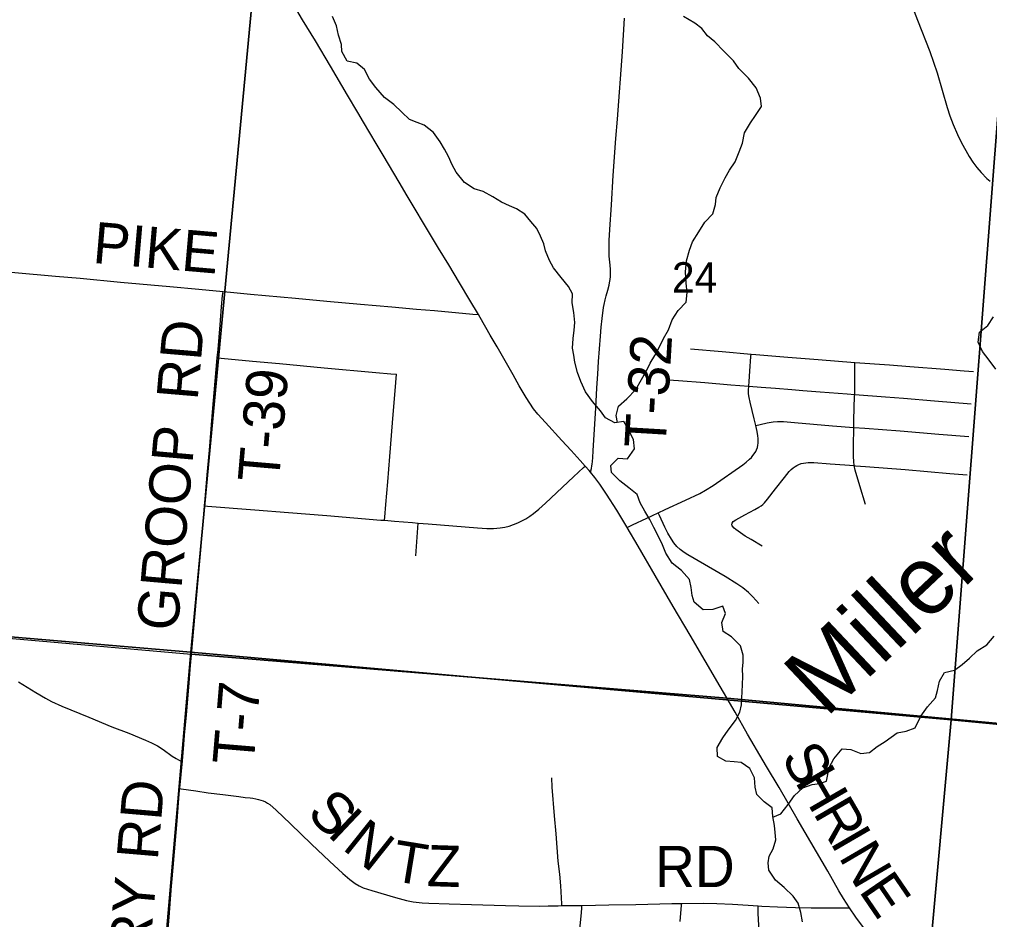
# Model space of a CAD drawing. Extents: x 0 to 1134, y 0 to 440.
# Drawn here: x 427.82 to 467.94, y 264.26 to 301.49 of the extents above; entities that cross this region are included whole.
import ezdxf

# ---------------------------------------------------------------- set-up
doc = ezdxf.new("R2010")
doc.units = 0
for name, color, linetype in [('GM_X_County_Road', 7, 'Continuous'), ('GM_X_County_Road_Text', 7, 'Continuous'), ('GM_X_Minor_River', 7, 'Continuous'), ('GM_X_Minor_River_Text', 7, 'Continuous'), ('GM_X_Section', 7, 'Continuous'), ('GM_X_Section_Text', 7, 'Continuous'), ('GM_X_Township', 7, 'Continuous'), ('GM_X_Township_Road', 7, 'Continuous'), ('GM_X_Township_Road_Text', 7, 'Continuous'), ('GM_X_Unincorporated', 7, 'Continuous')]:
    doc.layers.add(name, color=color, linetype=linetype)

msp = doc.modelspace()

# ---------------------------------------------------------------- linework, layer by layer
at = {"layer": 'GM_X_County_Road'}
for points in [[(446.801, 289.285), (446.446, 289.881), (446.016, 290.601), (445.575, 291.337), (445.153, 292.037), (444.864, 292.516), (443.858, 294.194), (443.525, 294.755), (442.86, 295.876), (442.574, 296.356), (442.054, 297.238), (441.818, 297.64), (441.388, 298.36), (440.68, 299.564), (440.063, 300.607), (439.53, 301.482), (439.195, 302.041), (438.86, 302.601), (438.148, 303.803), (437.714, 304.521), (437.366, 305.073), (437.237, 305.265)], [(406.575, 292.952), (407.128, 292.893), (408.056, 292.804), (408.89, 292.724), (410.284, 292.606), (411.397, 292.511), (412.736, 292.379), (414.46, 292.227), (416.686, 292.018), (417.522, 291.947), (418.542, 291.853), (420.676, 291.65), (422.19, 291.51), (424.667, 291.287), (425.874, 291.177), (427.638, 291.021), (429.308, 290.872), (430.33, 290.787), (432, 290.631), (434.042, 290.447), (435.244, 290.336), (436.24, 290.246)], [(436.24, 290.246), (436.547, 290.218), (437.38, 290.135), (439.235, 289.958), (440.534, 289.84), (441.927, 289.715), (443.226, 289.601), (444.247, 289.51), (444.989, 289.447), (446.567, 289.306), (446.801, 289.285)], [(451.216, 283.02), (451.013, 283.251), (450.636, 283.664), (450.255, 284.073), (449.57, 284.826), (449.258, 285.172), (449.085, 285.389), (448.924, 285.616), (448.773, 285.849), (448.49, 286.336), (448.234, 286.789), (447.795, 287.564), (447.57, 287.948), (447.291, 288.431), (446.875, 289.16), (446.801, 289.285)], [(451.435, 282.77), (451.383, 282.831), (451.216, 283.02)], [(452.948, 280.484), (452.935, 280.506), (452.53, 281.196), (452.104, 281.856), (451.824, 282.276), (451.617, 282.553), (451.435, 282.77)], [(457.074, 273.428), (456.801, 273.902), (455.563, 276.032), (454.861, 277.207), (454.115, 278.498), (453.402, 279.7), (452.948, 280.484)], [(462.142, 264.743), (461.899, 265.133), (461.712, 265.455), (461.245, 266.26), (460.315, 267.869), (459.988, 268.433), (459.232, 269.721), (458.713, 270.589), (458.575, 270.827), (457.93, 271.929), (457.413, 272.841), (457.089, 273.403), (457.074, 273.428)], [(465.836, 261.355), (465.183, 261.792), (464.659, 262.164), (464.501, 262.269), (464.354, 262.384), (464.065, 262.618), (463.713, 262.921), (463.509, 263.11), (463.175, 263.43), (462.925, 263.703), (462.688, 263.99), (462.408, 264.36), (462.142, 264.743)]]:
    msp.add_lwpolyline(points, dxfattribs=at)
at = {"layer": 'GM_X_Minor_River'}
for points in [[(455.635, 277.672), (455.605, 278.003), (455.53, 278.324), (455.204, 278.704), (454.809, 279.005), (454.552, 279.418), (454.42, 279.762), (454.275, 280.048), (454.053, 280.473), (453.886, 280.806), (453.685, 281.15), (453.496, 281.494), (453.363, 281.838), (453.025, 282.115), (452.652, 282.405), (452.303, 282.751), (452.273, 283.048), (452.584, 283.34), (452.972, 283.324), (453.25, 283.732), (453.221, 284.119), (452.987, 284.567), (452.82, 284.865), (452.443, 284.813), (452.058, 285.011), (451.845, 285.31), (451.52, 285.69), (451.228, 286.092), (451.04, 286.516), (450.897, 286.894), (450.788, 287.317), (450.746, 287.602), (450.693, 287.899), (450.72, 288.298), (450.759, 288.639), (450.786, 288.958), (450.745, 289.369), (450.682, 289.769), (450.698, 290.145), (450.531, 290.443), (450.228, 290.822), (449.902, 291.225), (449.735, 291.524), (449.581, 291.924), (449.504, 292.21), (449.372, 292.531), (449.216, 292.852), (448.969, 293.139), (448.722, 293.439), (448.383, 293.659), (448.088, 293.788), (447.759, 293.928), (447.397, 294.149), (447.001, 294.37), (446.627, 294.489), (446.231, 294.744), (445.883, 295.17), (445.716, 295.479), (445.561, 295.823), (445.405, 296.132), (445.226, 296.431), (444.946, 296.822), (444.563, 297.122), (444.268, 297.228), (443.95, 297.357), (443.635, 297.657), (443.308, 297.969), (442.913, 298.27), (442.554, 298.684), (442.296, 299.017), (442.095, 299.419), (441.78, 299.684), (441.37, 299.769), (441.148, 300.17), (441.14, 300.455), (441.019, 300.844), (440.933, 301.221), (440.767, 301.61)], [(452.55, 284.828), (452.504, 285.108), (452.6, 285.495), (452.934, 285.799), (453.315, 286.193), (453.548, 286.601), (453.77, 286.986), (453.91, 287.28), (454.096, 287.586), (454.259, 287.892), (454.458, 288.3), (454.668, 288.651), (454.81, 289.071), (455.065, 289.455), (455.389, 289.805), (455.428, 290.203), (455.398, 290.58), (455.359, 291.047), (455.41, 291.503), (455.529, 291.946), (455.648, 292.298), (455.915, 292.705), (456.171, 293.112), (456.494, 293.45), (456.601, 293.836), (456.639, 294.121), (456.792, 294.529), (457.002, 294.937), (457.189, 295.254), (457.421, 295.605), (457.585, 296.013), (457.715, 296.376), (457.8, 296.797), (458.056, 297.215), (458.265, 297.52), (458.509, 297.894), (458.468, 298.236), (458.291, 298.66), (457.965, 299.062), (457.571, 299.466), (457.347, 299.787), (456.953, 300.179), (456.571, 300.56), (456.278, 300.814), (456.042, 301.113), (455.748, 301.333), (455.285, 301.612)], [(468.198, 287.026), (467.928, 287.393), (467.647, 287.759), (467.468, 288.147), (467.528, 288.556), (467.871, 288.827), (468.101, 289.19)], [(460.205, 264.172), (460.13, 264.561), (460.021, 264.938), (459.819, 265.226), (459.448, 265.595), (459.087, 265.896), (458.808, 266.31), (458.789, 266.607), (458.826, 266.891), (458.99, 267.186), (459.097, 267.561), (459.067, 267.858), (459.048, 268.155), (458.972, 268.521), (458.954, 268.886), (458.616, 269.13), (458.312, 269.441), (458.247, 269.738), (458.218, 270.127), (458.029, 270.517), (457.668, 270.76), (457.383, 270.786), (457.03, 270.813), (456.691, 271.011), (456.673, 271.376), (456.906, 271.773), (457.126, 272.101), (457.428, 272.497), (457.614, 272.837), (457.686, 273.144), (457.72, 273.964), (457.736, 274.329), (457.728, 274.614), (457.743, 274.911), (457.747, 275.196), (457.638, 275.585), (457.266, 275.954), (456.916, 276.175), (456.863, 276.552), (457.016, 276.926), (456.906, 277.224), (456.494, 277.081), (456.095, 277.074), (455.723, 277.386), (455.635, 277.672)], [(463.621, 271.627), (464.12, 271.981), (464.495, 272.058), (464.86, 272.192), (465.09, 272.669), (465.366, 273.066), (465.709, 273.427), (465.78, 273.734), (465.862, 274.121), (466.08, 274.484), (466.49, 274.583), (466.809, 274.809), (467.106, 275.08), (467.427, 275.374), (467.826, 275.621), (468.135, 275.983)], [(458.977, 268.499), (459.304, 268.631), (459.606, 269.027), (459.873, 269.4), (460.218, 269.715), (460.607, 269.848), (460.916, 269.89), (461.202, 269.989), (461.3, 270.547), (461.498, 270.909), (461.846, 271.327), (462.198, 271.3), (462.618, 271.136), (462.972, 271.177), (463.294, 271.424), (463.621, 271.627)]]:
    msp.add_lwpolyline(points, dxfattribs=at)
at = {"layer": 'GM_X_Section'}
for points in [[(408.53, 307.786), (437.721, 305.198), (434.906, 275.318), (404.58, 277.901)], [(437.721, 305.198), (468.653, 302.376), (466.346, 272.53), (434.906, 275.318)], [(498.947, 299.62), (496.343, 269.642), (466.346, 272.53), (468.653, 302.376)], [(404.58, 277.901), (434.906, 275.318), (432.306, 245.32), (402.471, 248.078)], [(434.906, 275.318), (466.346, 272.53), (463.627, 242.452), (432.306, 245.32)], [(466.346, 272.53), (496.343, 269.642), (493.567, 239.575), (463.627, 242.452)]]:
    msp.add_lwpolyline(points, close=True, dxfattribs=at)
at = {"layer": 'GM_X_Township'}
msp.add_lwpolyline([(422.488, 276.334), (434.927, 275.233), (434.888, 274.78), (434.809, 273.869), (434.714, 272.73), (434.64, 271.886), (434.593, 271.344), (434.546, 270.823), (434.44, 269.701), (434.418, 269.457), (434.328, 268.343), (434.179, 266.58), (434.097, 265.655), (433.997, 264.363), (433.865, 262.785)], dxfattribs=at)
at = {"layer": 'GM_X_Township_Road'}
for p, q in [((444.21, 279.305), (444.307, 280.662)), ((434.447, 269.685), (434.553, 270.807))]:
    msp.add_line(p, q, dxfattribs=at)
for points in [[(464.659, 302.25), (464.952, 301.464), (465.466, 300.166), (465.623, 299.726), (465.765, 299.282), (466.18, 297.851), (466.298, 297.499), (466.431, 297.152), (466.618, 296.727), (466.78, 296.393), (466.958, 296.067), (467.094, 295.824), (467.243, 295.591), (467.407, 295.369), (467.588, 295.159), (467.832, 294.914), (467.965, 294.8)], [(451.435, 282.77), (451.473, 282.925), (451.497, 283.027), (451.511, 283.097), (451.525, 283.21), (451.533, 283.371), (451.549, 283.656), (451.61, 284.773), (451.652, 285.419), (451.703, 286.255), (451.733, 286.821), (451.764, 287.34), (451.845, 288.391), (451.881, 288.758), (451.918, 289.127), (451.975, 289.574), (452, 289.701), (452.045, 289.897), (452.091, 290.066), (452.158, 290.298), (452.206, 290.495), (452.228, 290.593), (452.249, 290.73), (452.264, 290.86), (452.268, 290.956), (452.263, 291.144), (452.245, 291.331), (452.208, 291.695), (452.204, 291.972), (452.205, 292.344), (452.23, 292.808), (452.3, 293.831), (452.375, 295.041), (452.481, 296.568), (452.549, 297.365), (452.755, 300.154), (452.847, 301.55)], [(436.001, 287.49), (436.033, 287.847), (436.123, 288.865), (436.181, 289.608), (436.224, 290.07), (436.24, 290.246)], [(455.577, 287.87), (456.886, 287.757), (458.081, 287.65)], [(435.475, 281.377), (435.512, 281.821), (435.587, 282.656), (435.678, 283.675), (435.804, 285.252), (435.958, 287.013), (436.001, 287.49)], [(436.001, 287.49), (436.16, 287.476), (437.459, 287.364), (438.572, 287.257), (440.426, 287.087), (442.56, 286.892), (443.176, 286.838), (443.412, 286.819)], [(457.979, 286.319), (457.994, 286.511), (458.029, 286.939), (458.073, 287.545), (458.081, 287.65)], [(458.081, 287.65), (458.27, 287.634), (459.594, 287.525), (460.854, 287.422), (462.367, 287.303)], [(462.361, 285.979), (462.361, 286.506), (462.366, 287.2), (462.367, 287.303)], [(462.367, 287.303), (463.803, 287.2), (464.645, 287.136), (466.093, 287.028), (466.895, 286.954), (467.274, 286.925)], [(442.924, 280.775), (442.934, 280.909), (442.973, 281.433), (443.05, 282.364), (443.134, 283.413), (443.248, 284.804), (443.388, 286.473), (443.412, 286.819)], [(454.661, 286.59), (455.08, 286.555), (456.158, 286.472), (457.236, 286.378), (457.979, 286.319)], [(458.269, 284.694), (458.206, 284.975), (458.033, 285.669), (457.994, 285.851), (457.97, 286.009), (457.97, 286.162), (457.979, 286.319)], [(457.979, 286.319), (458.491, 286.285), (459.092, 286.235), (459.766, 286.181), (460.219, 286.147), (460.933, 286.093), (462.056, 286.004), (462.361, 285.979)], [(462.321, 284.621), (462.331, 284.926), (462.356, 285.905), (462.361, 285.979)], [(462.361, 285.979), (463.631, 285.876), (464.379, 285.822), (465.664, 285.723), (467.171, 285.6)], [(458.269, 284.694), (458.447, 284.739), (458.742, 284.813), (458.984, 284.852), (459.166, 284.862), (459.422, 284.857), (459.87, 284.827), (461.445, 284.69), (462.321, 284.621)], [(454.24, 281.082), (454.524, 281.216), (455.366, 281.603), (455.956, 281.883), (456.198, 282.018), (456.511, 282.218), (457.731, 283.065), (457.879, 283.18), (458.018, 283.307), (458.088, 283.375), (458.152, 283.454), (458.211, 283.528), (458.27, 283.616), (458.304, 283.695), (458.339, 283.789), (458.358, 283.882), (458.363, 283.966), (458.363, 284.074), (458.363, 284.163), (458.354, 284.271), (458.324, 284.448), (458.269, 284.694)], [(462.346, 283.036), (462.321, 283.208), (462.312, 283.409), (462.312, 283.848), (462.321, 284.621)], [(462.321, 284.621), (462.784, 284.586), (464.247, 284.473), (465.837, 284.34), (467.077, 284.242)], [(444.307, 280.662), (444.722, 280.628), (446.769, 280.458), (447.144, 280.437), (447.426, 280.442), (447.707, 280.465), (447.893, 280.496), (448.077, 280.54), (448.256, 280.599), (448.431, 280.669), (448.602, 280.749), (448.767, 280.839), (448.926, 280.941), (449.078, 281.051), (449.296, 281.231), (449.573, 281.482), (450.727, 282.568), (451.15, 282.959), (451.216, 283.02)], [(458.54, 279.712), (458.076, 279.977), (457.837, 280.126), (457.451, 280.394), (457.374, 280.453), (457.294, 280.543), (457.28, 280.588), (457.29, 280.653), (457.334, 280.722), (457.448, 280.795), (457.822, 280.997), (458.235, 281.229), (458.398, 281.317), (458.491, 281.371), (458.56, 281.43), (458.629, 281.499), (458.752, 281.657), (459.092, 282.08), (459.456, 282.548), (459.653, 282.794), (459.737, 282.883), (459.821, 282.952), (459.894, 283.001), (459.968, 283.045), (460.052, 283.085), (460.145, 283.119), (460.239, 283.139), (460.342, 283.159), (460.436, 283.168), (460.667, 283.163), (461.342, 283.114), (461.947, 283.075), (462.346, 283.036)], [(462.346, 283.036), (462.399, 283.033), (462.809, 283.006), (464.448, 282.878), (466.299, 282.715), (467.008, 282.656)], [(462.809, 281.425), (462.573, 282.199), (462.386, 282.843), (462.346, 283.036)], [(434.934, 275.217), (435.086, 276.92), (435.212, 278.31), (435.373, 280.164), (435.475, 281.377)], [(435.475, 281.377), (435.605, 281.366), (437.559, 281.21), (438.954, 281.095), (440.536, 280.969), (442.769, 280.788), (442.924, 280.775)], [(452.948, 280.484), (453.178, 280.589), (453.769, 280.86), (454.24, 281.082)], [(458.404, 277.329), (458.154, 277.612), (457.971, 277.79), (457.741, 277.987), (457.486, 278.155), (457.001, 278.448), (455.463, 279.347), (455.309, 279.448), (455.142, 279.57), (455.009, 279.698), (454.889, 279.839), (454.78, 279.989), (454.636, 280.241), (454.507, 280.49), (454.291, 280.971), (454.24, 281.082)], [(442.924, 280.775), (443.327, 280.74), (444.071, 280.682), (444.307, 280.662)], [(434.553, 270.807), (434.6, 271.328), (434.647, 271.87), (434.721, 272.714), (434.816, 273.853), (434.895, 274.764), (434.934, 275.217)], [(427.788, 274.092), (428.504, 273.656), (428.906, 273.418), (429.154, 273.287), (429.579, 273.092), (430.697, 272.627), (431.645, 272.235), (432.339, 271.965), (433.031, 271.689), (433.284, 271.574), (433.528, 271.444), (433.763, 271.296), (434.142, 271.025), (434.3, 270.923), (434.396, 270.867), (434.453, 270.839), (434.504, 270.82), (434.553, 270.807)], [(450.254, 264.837), (450.251, 264.91), (450.241, 265.16), (450.212, 265.663), (450.164, 266.134), (450.105, 266.671), (450.019, 267.807), (449.954, 268.549), (449.858, 269.744), (449.834, 270.124)], [(433.059, 253.18), (433.056, 253.213), (433.063, 253.494), (433.091, 253.866), (433.206, 255.164), (433.435, 257.854), (433.548, 259.153), (433.683, 260.637), (433.872, 262.769), (434.004, 264.347), (434.104, 265.639), (434.186, 266.564), (434.335, 268.327), (434.425, 269.441), (434.447, 269.685)], [(434.447, 269.685), (434.515, 269.675), (435.11, 269.591), (435.628, 269.51), (436.233, 269.433), (436.89, 269.348), (437.16, 269.316), (437.356, 269.293), (437.477, 269.279), (437.594, 269.257), (437.702, 269.234), (437.806, 269.206), (437.902, 269.173), (437.991, 269.129), (438.076, 269.079), (438.172, 269.016), (438.435, 268.79), (439.035, 268.22), (439.902, 267.375), (440.647, 266.672), (441.195, 266.168), (441.48, 265.925), (441.704, 265.754), (441.865, 265.655), (442.038, 265.578), (442.394, 265.462), (443.378, 265.18), (443.828, 265.056), (444.102, 264.997), (444.475, 264.96), (444.755, 264.941), (445.591, 264.917), (446.521, 264.887), (447.918, 264.846), (448.477, 264.835), (449.315, 264.823), (449.687, 264.829), (450.104, 264.834), (450.254, 264.837)], [(450.18, 256.374), (450.194, 256.518), (450.253, 257.182), (450.329, 258.032), (450.42, 259.056), (450.532, 260.065), (450.656, 261.083), (450.759, 261.868), (450.848, 262.597), (450.924, 263.258), (451.007, 264.001), (451.061, 264.545), (451.075, 264.748), (451.082, 264.85)], [(450.254, 264.837), (450.891, 264.847), (451.082, 264.85)], [(451.082, 264.85), (451.637, 264.858), (452.196, 264.87), (453.314, 264.892), (454.804, 264.924), (455.195, 264.928)], [(455.195, 264.928), (455.189, 264.86), (455.129, 264.184)], [(455.195, 264.928), (456.107, 264.938), (456.664, 264.925), (457.313, 264.897), (457.961, 264.858), (458.369, 264.831), (458.518, 264.821), (459.17, 264.79), (459.916, 264.766), (460.568, 264.75), (461.295, 264.743), (462.019, 264.745), (462.142, 264.743)], [(458.414, 263.783), (458.37, 264.519), (458.365, 264.667), (458.368, 264.789), (458.369, 264.831)]]:
    msp.add_lwpolyline(points, dxfattribs=at)
at = {"layer": 'GM_X_Unincorporated'}
for points in [[(422.488, 276.334), (434.927, 275.233), (457.082, 273.419), (483.608, 270.953), (488.235, 270.514), (494.041, 269.799)], [(494.041, 269.799), (488.235, 270.514), (483.608, 270.953), (457.082, 273.419), (434.927, 275.233), (434.888, 274.78), (434.809, 273.869), (434.714, 272.73), (434.64, 271.886), (434.593, 271.344), (434.546, 270.823), (434.44, 269.701), (434.418, 269.457), (434.328, 268.343), (434.179, 266.58), (434.097, 265.655), (433.997, 264.363), (433.865, 262.785)]]:
    msp.add_lwpolyline(points, dxfattribs=at)

# ---------------------------------------------------------------- texts
at = {"layer": 'GM_X_County_Road_Text'}
for s, height, rotation, p in [('PIKE', 1.7045, 355.0567, (430.82, 291.426)), ('S', 1.705, 300.135, (459.288, 270.968)), ('H', 1.705, 300.1335, (459.866, 269.973)), ('R', 1.705, 300.1322, (460.619, 268.676)), ('I', 1.705, 300.1439, (461.321, 267.465)), ('N', 1.705, 300.2948, (461.675, 266.855)), ('E', 1.705, 304.3702, (462.503, 265.448))]:
    msp.add_text(s, height=height, rotation=rotation, dxfattribs=at).set_placement(p)
at = {"layer": 'GM_X_Minor_River_Text'}
msp.add_text('Miller', height=2.8426, rotation=43.3539, dxfattribs=at).set_placement((461.164, 272.573))
at = {"layer": 'GM_X_Section_Text'}
msp.add_text('24', height=1.2557, rotation=0, dxfattribs=at).set_placement((454.806, 290.195))
at = {"layer": 'GM_X_Township_Road_Text'}
for s, height, rotation, p in [('RD', 1.7045, 85.1131, (435.188, 285.712)), ('T-32', 1.7045, 86.5979, (454.536, 283.729)), ('T-39', 1.7045, 85.0756, (438.546, 282.302)), ('GROOP', 1.7045, 84.9678, (434.363, 276.163)), ('T-7', 1.7045, 85.2348, (437.503, 270.616)), ('RD', 1.7045, 85.0738, (433.539, 266.691)), ('S', 1.705, 315.9431, (439.654, 268.596)), ('I', 1.705, 316.6682, (440.504, 267.774)), ('N', 1.705, 321.4964, (441.127, 267.195)), ('T', 1.705, 350.666, (443.161, 265.879)), ('Z', 1.705, 358.1557, (444.659, 265.648)), ('RD', 1.7045, 0, (454.106, 265.604)), ('VICTORY', 1.7045, 84.9299, (432.588, 255.842))]:
    msp.add_text(s, height=height, rotation=rotation, dxfattribs=at).set_placement(p)

doc.saveas('drawing.dxf')
